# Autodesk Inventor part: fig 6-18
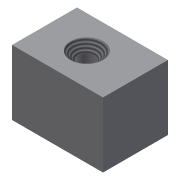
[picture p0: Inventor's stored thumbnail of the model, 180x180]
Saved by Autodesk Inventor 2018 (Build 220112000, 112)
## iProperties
Created: 2009-09
Part Number: fig 6-18
Document SubType Name: Modeling
Designer: Sham
Density: 1 g/cm^3
Material: Generic
Appearance: Default
Author: Sham
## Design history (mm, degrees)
sketch "Sketch1"
  geometry: L1 (-28, 20)-(0, 20); L2 (0, 20)-(0, 0); L3 (0, 0)-(-28, 0); L4 (-28, 0)-(-28, 20)
  constraints: 8 end point, 2 parallel, 1 horizontal, 1 perpendicular
extrude "Extrusion1" new body sketch "Sketch1" distance "d0" = 20; taper "d1" = 0 deg
hole "Hole1" diameter "d4" = 5; stored, may be unused: countersink angle "d8" = 90 deg, drill point angle "d10" = 118 deg; dims "d2" = 10, "d3" = 15, "d5" = 5.946, "d6" = 10, "d7" = 3, "d9" = 15, "d11" = 0.62479, "d12" = 5.994
thread "Thread1" dims "d13" = 10, "d14" = 0
body "Solid1"
